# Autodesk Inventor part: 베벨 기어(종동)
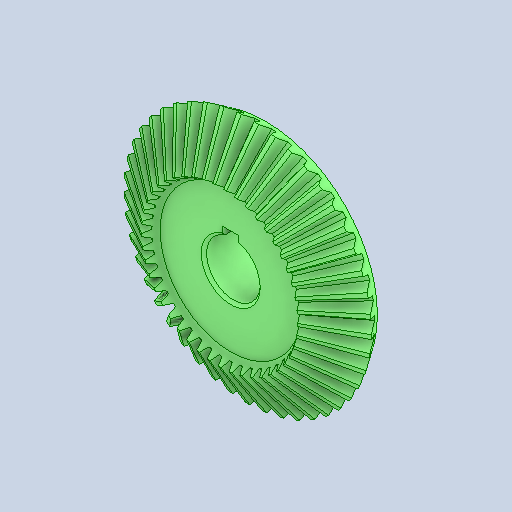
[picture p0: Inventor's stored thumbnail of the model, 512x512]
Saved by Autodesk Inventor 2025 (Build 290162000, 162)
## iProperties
Created: 2026-01
Part Number: 베벨 기어(종동)
Material: 강철, 합금
Document SubType Name: Modeling
Designer: KDI
Density: 7.73 g/cm^3
Appearance: 기본값
Author: jhkim
Sending System: Autodesk Inventor 2026
Preprocessor: ST-DEVELOPER v20.1
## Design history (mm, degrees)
feature "Solid1"
node "솔리드1"
